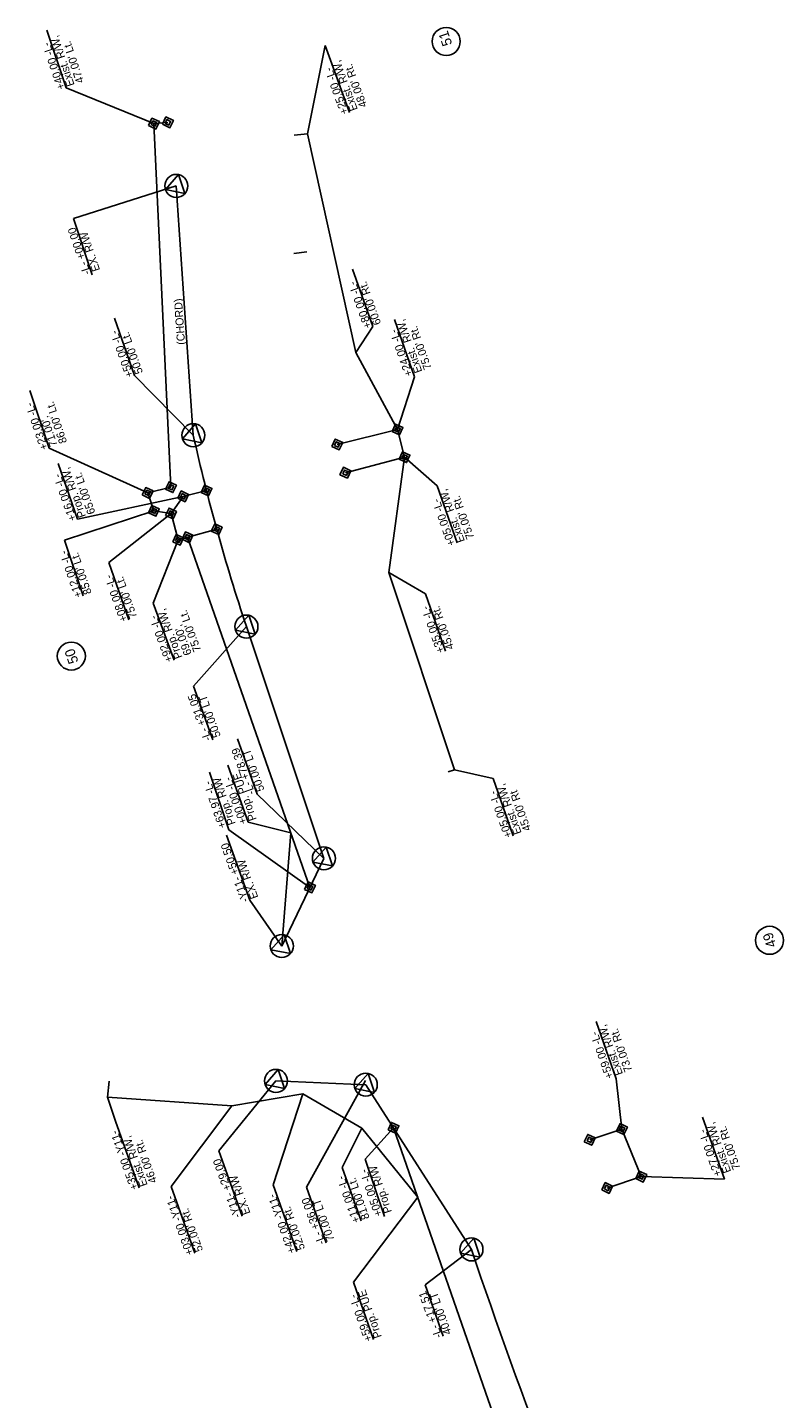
# Model space of a CAD drawing. Extents: x 1610947 to 1617684, y 899814 to 904658.
# Drawn here: x 1615897 to 1616369, y 903801 to 904658 of the extents above; entities that cross this region are included whole.
import ezdxf

# ---------------------------------------------------------------- set-up
doc = ezdxf.new("R2010")
doc.units = 0
for name, color, linetype in [('Prop Conc 1ft 6in Curb and Gutter', 7, 'Continuous'), ('Prop EOT Dash', 7, 'Continuous'), ('Prop Hatching', 7, 'Continuous'), ('Prop Horizontal Alignment Curve and Spiral Data', 7, 'Continuous'), ('Prop Horizontal Alignment Direction Label', 7, 'Continuous'), ('Prop Horizontal Alignment Tick Label', 7, 'Continuous'), ('Prop Horizontal Alignment Tick Large', 7, 'Continuous'), ('Prop Horizontal Alignment Tick Small', 7, 'Continuous'), ('Prop ROW Marker CELL', 7, 'Continuous'), ('Prop ROW RW Lines', 7, 'Continuous'), ('Prop ROW Station Offsets', 7, 'Continuous'), ('Scratch_Level_3', 7, 'Continuous'), ('Scratch_Level_8', 7, 'Continuous'), ('Typical Terminator CELL', 7, 'Continuous')]:
    doc.layers.add(name, color=color, linetype=linetype)

msp = doc.modelspace()

# ---------------------------------------------------------------- linework, layer by layer
at = {"layer": 'Prop Conc 1ft 6in Curb and Gutter'}
for p, q in [((1616082.67, 904646.44), (1616071.76, 904591.28)), ((1616082.67, 904646.44), (1616097.89, 904604.73)), ((1616099.82, 904506.76), (1616112.47, 904471.01)), ((1616145.36, 904303.99), (1616158, 904268.24)), ((1616022.04, 904197.04), (1616034.69, 904161.29)), ((1616187.59, 904188.55), (1616200.24, 904152.81)), ((1615951.85, 903974.58), (1615966.6, 903932.87)), ((1616093.4, 903945.73), (1616105.25, 903912.24)), ((1616050.2, 903934.9), (1616064.95, 903893.2)), ((1615986.48, 903933.79), (1616001.22, 903892.08)), ((1616100.35, 903873.94), (1616140.55, 903927.03)), ((1616100.35, 903873.94), (1616112.89, 903838.16))]:
    msp.add_line(p, q, dxfattribs=at)
for points in [[(1616112.47, 904471.01), (1616101.91, 904454.84)], [(1616145.36, 904303.99), (1616122.46, 904317.27)], [(1616187.59, 904188.55), (1616163.62, 904194.12)], [(1616034.69, 904161.29), (1616061.34, 904154.66)], [(1615951.85, 903974.58), (1615946.8, 903989.62)], [(1616050.2, 903934.9), (1616068.76, 903991.57)], [(1615986.48, 903933.79), (1616024.45, 903984.24)], [(1616093.4, 903945.73), (1616105.62, 903970.18)]]:
    msp.add_lwpolyline(points, dxfattribs=at)
at = {"layer": 'Prop EOT Dash'}
for points in [[(1615972.41, 904596.48), (1615974.56, 904601.1), (1615979.18, 904598.95), (1615977.03, 904594.34)], [(1615974.11, 904597.1), (1615975.18, 904599.41), (1615977.49, 904598.33), (1615976.41, 904596.03)], [(1615981.14, 904597.27), (1615983.29, 904601.88), (1615987.9, 904599.74), (1615985.76, 904595.12)], [(1615982.83, 904597.88), (1615983.9, 904600.19), (1615986.21, 904599.12), (1615985.14, 904596.81)], [(1616124.55, 904405.37), (1616126.69, 904409.99), (1616131.31, 904407.84), (1616129.16, 904403.22)], [(1616126.24, 904405.99), (1616127.31, 904408.3), (1616129.62, 904407.22), (1616128.54, 904404.91)], [(1616086.93, 904396.1), (1616089.08, 904400.71), (1616093.69, 904398.56), (1616091.54, 904393.95)], [(1616088.62, 904396.71), (1616089.69, 904399.02), (1616092, 904397.95), (1616090.93, 904395.64)], [(1616128.94, 904388.16), (1616131.09, 904392.78), (1616135.7, 904390.63), (1616133.56, 904386.02)], [(1616130.63, 904388.78), (1616131.7, 904391.09), (1616134.01, 904390.01), (1616132.94, 904387.71)], [(1616091.98, 904378.4), (1616094.13, 904383.02), (1616098.75, 904380.87), (1616096.6, 904376.25)], [(1616093.68, 904379.02), (1616094.75, 904381.33), (1616097.06, 904380.25), (1616095.98, 904377.94)], [(1615983.05, 904369.39), (1615985.19, 904374), (1615989.81, 904371.86), (1615987.66, 904367.24)], [(1615984.74, 904370), (1615985.81, 904372.31), (1615988.12, 904371.24), (1615987.04, 904368.93)], [(1616005.21, 904367.35), (1616007.35, 904371.96), (1616011.97, 904369.82), (1616009.82, 904365.2)], [(1615968.48, 904365.78), (1615970.63, 904370.4), (1615975.25, 904368.25), (1615973.1, 904363.64)], [(1615970.18, 904366.4), (1615971.25, 904368.71), (1615973.56, 904367.63), (1615972.48, 904365.33)], [(1615990.67, 904363.66), (1615992.82, 904368.27), (1615997.43, 904366.12), (1615995.28, 904361.51)], [(1615992.36, 904364.27), (1615993.43, 904366.58), (1615995.74, 904365.51), (1615994.67, 904363.2)], [(1616006.9, 904367.96), (1616007.97, 904370.27), (1616010.28, 904369.2), (1616009.21, 904366.89)], [(1615972.35, 904354.57), (1615974.5, 904359.19), (1615979.11, 904357.04), (1615976.96, 904352.42)], [(1615974.04, 904355.19), (1615975.11, 904357.5), (1615977.42, 904356.42), (1615976.35, 904354.11)], [(1615983.1, 904352.94), (1615985.25, 904357.56), (1615989.87, 904355.41), (1615987.72, 904350.79)], [(1615984.79, 904353.56), (1615985.87, 904355.87), (1615988.17, 904354.79), (1615987.1, 904352.48)], [(1616011.62, 904343.14), (1616013.77, 904347.76), (1616018.39, 904345.61), (1616016.24, 904340.99)], [(1616013.31, 904343.76), (1616014.39, 904346.07), (1616016.7, 904344.99), (1616015.62, 904342.68)], [(1615987.53, 904336.48), (1615989.67, 904341.1), (1615994.29, 904338.95), (1615992.14, 904334.34)], [(1615989.22, 904337.1), (1615990.29, 904339.41), (1615992.6, 904338.33), (1615991.53, 904336.03)], [(1615993.31, 904338.08), (1615995.46, 904342.7), (1616000.07, 904340.55), (1615997.93, 904335.93)], [(1615995, 904338.7), (1615996.07, 904341.01), (1615998.38, 904339.93), (1615997.31, 904337.62)], [(1616069.87, 904119.41), (1616072.02, 904124.03), (1616076.63, 904121.88), (1616074.49, 904117.26)], [(1616071.56, 904120.03), (1616072.63, 904122.34), (1616074.94, 904121.26), (1616073.87, 904118.95)], [(1616122.02, 903969.23), (1616124.17, 903973.85), (1616128.78, 903971.7), (1616126.63, 903967.08)], [(1616123.71, 903969.85), (1616124.78, 903972.16), (1616127.09, 903971.08), (1616126.02, 903968.77)], [(1616264.78, 903968.45), (1616266.93, 903973.07), (1616271.54, 903970.92), (1616269.4, 903966.3)], [(1616266.47, 903969.07), (1616267.55, 903971.37), (1616269.85, 903970.3), (1616268.78, 903967.99)], [(1616244.63, 903961.71), (1616246.77, 903966.33), (1616251.39, 903964.18), (1616249.24, 903959.56)], [(1616246.32, 903962.33), (1616247.39, 903964.64), (1616249.7, 903963.56), (1616248.63, 903961.26)], [(1616276.83, 903938.74), (1616278.98, 903943.35), (1616283.59, 903941.2), (1616281.44, 903936.59)], [(1616255.51, 903931.61), (1616257.66, 903936.23), (1616262.27, 903934.08), (1616260.13, 903929.46)], [(1616257.2, 903932.23), (1616258.28, 903934.54), (1616260.58, 903933.46), (1616259.51, 903931.15)], [(1616278.52, 903939.35), (1616279.59, 903941.66), (1616281.9, 903940.59), (1616280.83, 903938.28)]]:
    msp.add_lwpolyline(points, close=True, dxfattribs=at)
at = {"layer": 'Prop Hatching'}
for centre in [(1616158.36, 904649.05), (1615924.17, 904265.11), (1616360.36, 904087.56)]:
    msp.add_circle(centre, 8.75, dxfattribs=at)
at = {"layer": 'Prop Horizontal Alignment Curve and Spiral Data'}
for p, q in [((1615915.92, 904385.35), (1615928.06, 904350.69)), ((1615947.52, 904323.53), (1615960.05, 904287.75)), ((1615975.37, 904298.15), (1615988.37, 904262.52))]:
    msp.add_line(p, q, dxfattribs=at)
for points in [[(1615928.06, 904350.69), (1615994.05, 904364.89)], [(1615947.52, 904323.53), (1615986.48, 904354.18)], [(1615975.37, 904298.15), (1615990.91, 904337.72)]]:
    msp.add_lwpolyline(points, dxfattribs=at)
at = {"layer": 'Prop Horizontal Alignment Direction Label'}
for p, q in [((1615975.8, 904597.72), (1615984.52, 904598.5)), ((1615986.43, 904370.62), (1615975.8, 904597.72)), ((1615986.43, 904370.62), (1615971.87, 904367.02)), ((1615975.73, 904355.8), (1615971.87, 904367.02)), ((1615986.48, 904354.18), (1615975.73, 904355.8)), ((1616073.25, 904120.64), (1615996.69, 904339.31)), ((1616257.65, 903591.25), (1616125.4, 903970.47))]:
    msp.add_line(p, q, dxfattribs=at)
at = {"layer": 'Prop Horizontal Alignment Tick Label'}
for p, q in [((1615908.85, 904656.06), (1615920.91, 904620.11)), ((1615920.91, 904620.11), (1615975.8, 904597.72)), ((1615898.25, 904430.99), (1615910.31, 904395.04)), ((1615919.95, 904337.52), (1615931.62, 904302.71)), ((1616010.55, 904192.58), (1616022.61, 904156.63)), ((1616022.61, 904156.63), (1616073.25, 904120.64)), ((1616107.71, 903950.91), (1616125.4, 903970.47)), ((1616107.71, 903950.91), (1616119.77, 903914.96))]:
    msp.add_line(p, q, dxfattribs=at)
for points in [[(1615910.31, 904395.04), (1615971.87, 904367.02)], [(1615919.95, 904337.52), (1615975.73, 904355.8)]]:
    msp.add_lwpolyline(points, dxfattribs=at)
at = {"layer": 'Prop Horizontal Alignment Tick Large'}
for p, q in [((1615994.05, 904364.89), (1615986.48, 904354.18)), ((1616008.59, 904368.58), (1615994.05, 904364.89)), ((1615990.91, 904337.72), (1615986.48, 904354.18)), ((1616015.01, 904344.37), (1615990.91, 904337.72))]:
    msp.add_line(p, q, dxfattribs=at)
at = {"layer": 'Prop ROW Marker CELL'}
for p, q in [((1615975.8, 904597.72), (1615975.8, 904597.72)), ((1615984.52, 904598.5), (1615984.52, 904598.5)), ((1615989.74, 904558.81), (1615989.74, 904558.81)), ((1616127.93, 904406.61), (1616127.93, 904406.61)), ((1616000.36, 904403.09), (1616000.36, 904403.09)), ((1616090.31, 904397.33), (1616090.31, 904397.33)), ((1616132.32, 904389.4), (1616132.32, 904389.4)), ((1616095.37, 904379.63), (1616095.37, 904379.63)), ((1615971.87, 904367.02), (1615971.87, 904367.02)), ((1615986.43, 904370.62), (1615986.43, 904370.62)), ((1615994.05, 904364.89), (1615994.05, 904364.89)), ((1616008.59, 904368.58), (1616008.59, 904368.58)), ((1615975.73, 904355.8), (1615975.73, 904355.8)), ((1615986.48, 904354.18), (1615986.48, 904354.18)), ((1615990.91, 904337.72), (1615990.91, 904337.72)), ((1615996.69, 904339.31), (1615996.69, 904339.31)), ((1616015.01, 904344.37), (1616015.01, 904344.37)), ((1616033.56, 904283.55), (1616033.56, 904283.55)), ((1616081.96, 904138.77), (1616081.96, 904138.77)), ((1616073.25, 904120.64), (1616073.25, 904120.64)), ((1616055.66, 904084.01), (1616055.66, 904084.01)), ((1616052.01, 903999.76), (1616052.01, 903999.76)), ((1616108.13, 903997.38), (1616108.13, 903997.38)), ((1616125.4, 903970.47), (1616125.4, 903970.47)), ((1616268.16, 903969.68), (1616268.16, 903969.68)), ((1616248.01, 903962.95), (1616248.01, 903962.95)), ((1616280.21, 903939.97), (1616280.21, 903939.97)), ((1616258.89, 903932.84), (1616258.89, 903932.84)), ((1616174.14, 903894.51), (1616174.14, 903894.51))]:
    msp.add_line(p, q, dxfattribs=at)
for points in [[(1615995.14, 904554.03), (1615982.91, 904556.52), (1615991.16, 904565.88)], [(1616005.77, 904398.31), (1615993.54, 904400.8), (1616001.79, 904410.16)], [(1616038.96, 904278.77), (1616026.74, 904281.26), (1616034.99, 904290.62)], [(1616087.36, 904133.99), (1616075.13, 904136.48), (1616083.38, 904145.84)], [(1616061.06, 904079.23), (1616048.83, 904081.72), (1616057.08, 904091.08)], [(1616057.41, 903994.98), (1616045.19, 903997.47), (1616053.44, 904006.83)], [(1616113.53, 903992.6), (1616101.3, 903995.09), (1616109.55, 904004.45)], [(1616179.55, 903889.73), (1616167.32, 903892.22), (1616175.57, 903901.58)]]:
    msp.add_lwpolyline(points, close=True, dxfattribs=at)
for centre in [(1615989.74, 904558.81), (1616000.36, 904403.09), (1616033.56, 904283.55), (1616081.96, 904138.77), (1616055.66, 904084.01), (1616052.01, 903999.76), (1616108.13, 903997.38), (1616174.14, 903894.51)]:
    msp.add_circle(centre, 7.2, dxfattribs=at)
at = {"layer": 'Prop ROW RW Lines'}
for p, q in [((1616000.36, 904403.09), (1615989.74, 904558.81)), ((1616071.35, 904517.66), (1616063.19, 904516.58)), ((1616081.96, 904138.77), (1616033.56, 904283.55)), ((1616055.66, 904084.01), (1616081.96, 904138.77)), ((1616052.01, 903999.76), (1616108.13, 903997.38)), ((1616174.14, 903894.51), (1616108.13, 903997.38))]:
    msp.add_line(p, q, dxfattribs=at)
for centre, radius, start, end in [((1617171.66, 904663.97), 1200, 192.55619, 198.48273), ((1619057.34, 904858.25), 3040, 198.48273, 204.08027)]:
    msp.add_arc(centre, radius, start, end, dxfattribs=at)
at = {"layer": 'Prop ROW Station Offsets'}
for p, q in [((1615925.47, 904538.37), (1615989.74, 904558.81)), ((1615925.47, 904538.37), (1615937.22, 904503.34)), ((1615951.04, 904476.14), (1615963.72, 904440.41)), ((1616000.58, 904246.22), (1616033.56, 904283.55)), ((1616000.58, 904246.22), (1616012.56, 904212.71)), ((1616027.91, 904213.45), (1616040.31, 904178.78)), ((1616040.31, 904178.78), (1616081.96, 904138.77)), ((1616021.14, 904153.27), (1616035.71, 904112.54)), ((1616035.71, 904112.54), (1616055.66, 904084.01)), ((1616016.27, 903956.02), (1616052.01, 903999.76)), ((1616071, 903933.38), (1616107.84, 903999.98)), ((1616016.27, 903956.02), (1616030.84, 903915.29)), ((1616071, 903933.38), (1616083.34, 903898.64)), ((1616145.13, 903872.27), (1616156.47, 903840.32))]:
    msp.add_line(p, q, dxfattribs=at)
for points in [[(1615963.72, 904440.41), (1616000.36, 904403.09)], [(1616145.13, 903872.27), (1616174.14, 903894.51), (1616174.14, 903894.51)]]:
    msp.add_lwpolyline(points, dxfattribs=at)
at = {"layer": 'Scratch_Level_3'}
for p, q in [((1616071.76, 904591.28), (1616063.48, 904590.53)), ((1616101.91, 904454.84), (1616071.76, 904591.28)), ((1616127.93, 904406.61), (1616101.91, 904454.84)), ((1616122.46, 904317.27), (1616132.32, 904389.4)), ((1616163.62, 904194.12), (1616122.46, 904317.27)), ((1616159.52, 904192.75), (1616163.62, 904194.12)), ((1616055.66, 904084.01), (1616061.34, 904154.66)), ((1615946.8, 903989.62), (1615947.72, 903999.64)), ((1616024.45, 903984.24), (1615946.8, 903989.62)), ((1616068.76, 903991.57), (1616024.45, 903984.24)), ((1616105.62, 903970.18), (1616068.76, 903991.57)), ((1616140.55, 903927.03), (1616105.62, 903970.18))]:
    msp.add_line(p, q, dxfattribs=at)
at = {"layer": 'Scratch_Level_8'}
for p, q in [((1616126.09, 904475.33), (1616138.62, 904439.54)), ((1616138.62, 904439.54), (1616127.93, 904406.61)), ((1616152.72, 904371.53), (1616132.32, 904389.4)), ((1616152.72, 904371.53), (1616165.26, 904335.75)), ((1616252.06, 904036.87), (1616264.6, 904001.08)), ((1616264.6, 904001.08), (1616268.16, 903969.68)), ((1616318.55, 903977.09), (1616332.13, 903938.33)), ((1616332.13, 903938.33), (1616280.21, 903939.97))]:
    msp.add_line(p, q, dxfattribs=at)
at = {"layer": 'Typical Terminator CELL'}
for p, q in [((1616127.93, 904406.61), (1616090.31, 904397.33)), ((1616132.32, 904389.4), (1616127.93, 904406.61)), ((1616095.37, 904379.63), (1616132.32, 904389.4)), ((1616268.16, 903969.68), (1616248.01, 903962.95)), ((1616280.21, 903939.97), (1616268.16, 903969.68)), ((1616258.89, 903932.84), (1616280.21, 903939.97))]:
    msp.add_line(p, q, dxfattribs=at)

# ---------------------------------------------------------------- texts
at = {"layer": 'Prop Conc 1ft 6in Curb and Gutter'}
for s, rotation, p in [('Exist. R/W,', 110.05109, (1616103.17, 904606.65)), ('+25.00 -L-', 110.05109, (1616097.3, 904604.51)), ("48.00' Rt.", 110.05109, (1616109.05, 904608.8)), ('+80.00 -L-', 109.47574, (1616111.88, 904470.8)), ("60.00' Rt.", 109.47574, (1616117.77, 904472.88)), ('+35.00 -L-', 109.47574, (1616157.41, 904268.03)), ("45.00' Rt.", 109.47574, (1616163.3, 904270.11)), ('Prop. PUE', 109.47574, (1616039.99, 904163.17)), ('+00.00 -L-', 109.47574, (1616034.1, 904161.09)), ('Exist. R/W,', 109.47574, (1616205.54, 904154.68)), ('+05.00 -L-', 109.47574, (1616199.65, 904152.6)), ("45.00' Rt", 109.47574, (1616211.43, 904156.77)), ('+35.00 -Y11-', 109.47574, (1615966.01, 903932.66)), ('Exist. R/W,', 109.47574, (1615971.9, 903934.75)), ("46.00' Rt.", 109.47574, (1615977.79, 903936.83)), ('+11.00 -L-', 109.47574, (1616104.66, 903912.03)), ("81.00' Lt.", 109.47574, (1616110.55, 903914.12)), ('+03.00 -Y11-', 109.47574, (1616000.63, 903891.88)), ('+42.00 -Y11-', 109.47574, (1616064.36, 903892.99)), ("52.00' Rt.", 109.47574, (1616006.53, 903893.96)), ("52.00' Rt.", 109.47574, (1616070.25, 903895.08)), ('+59.00 -L-', 109.30477, (1616112.3, 903837.95)), ('Prop. PUE', 109.30477, (1616118.2, 903840.02))]:
    msp.add_text(s, height=5, rotation=rotation, dxfattribs=at).set_placement(p)
at = {"layer": 'Prop Hatching'}
for s, p in [('51', (1616162.23, 904647.42)), ('50', (1615928.69, 904261.56)), ('49', (1616364.81, 904084.25))]:
    msp.add_text(s, height=6.25, rotation=109.01556, dxfattribs=at).set_placement(p)
at = {"layer": 'Prop Horizontal Alignment Curve and Spiral Data'}
for s, rotation, p in [('Prop. R/W,', 109.30477, (1615933.37, 904352.55)), ("65.00' Lt.", 109.30477, (1615939.27, 904354.62)), ('+16.00 -L-', 109.30477, (1615927.47, 904350.49)), ('+08.00 -L-', 109.30477, (1615959.46, 904287.54)), ("75.00' Lt.", 109.30477, (1615965.36, 904289.61)), ('Prop. R/W,', 110.05109, (1615993.65, 904264.45)), ("75.00' Lt.", 110.05109, (1616005.4, 904268.74)), ('+92.00 -L-', 110.05109, (1615987.78, 904262.31)), ("69.00',", 110.05109, (1615999.53, 904266.6))]:
    msp.add_text(s, height=5, rotation=rotation, dxfattribs=at).set_placement(p)
at = {"layer": 'Prop Horizontal Alignment Tick Label'}
for s, p in [('+40.00 -L-', (1615920.31, 904619.91)), ('Exist. R/W,', (1615926.24, 904621.9)), ("47.00' Lt.", (1615932.17, 904623.88)), ('+23.00 -L-', (1615909.71, 904394.84)), ("86.00' Lt.", (1615921.57, 904398.81)), ("71.00',", (1615915.64, 904396.83)), ('+12.00 -L-', (1615931.03, 904302.51)), ("85.00' Lt.", (1615936.96, 904304.5)), ('+63.97 -L-', (1616021.01, 904158.53)), ('Prop. R/W', (1616026.94, 904160.52)), ('+05.00 -L-', (1616118.56, 903916.06)), ('Prop. R/W', (1616124.49, 903918.04))]:
    msp.add_text(s, height=5, rotation=108.54317, dxfattribs=at).set_placement(p)
at = {"layer": 'Prop Horizontal Alignment Tick Small'}
msp.add_text('(CHORD)', height=5, rotation=93.90477, dxfattribs=at).set_placement((1615995.25, 904459.71))
at = {"layer": 'Prop ROW Station Offsets'}
for s, rotation, p in [('-L- +00.00', 108.54317, (1615936.25, 904504.31)), ('EX. R/W', 108.54317, (1615942.17, 904506.3)), ('+50.00 -L-', 109.54863, (1615963.13, 904440.2)), ("50.00' Lt.", 109.54863, (1615969.02, 904442.29)), ('-L- +31.05', 109.68596, (1616011.73, 904213.1)), ("50.00' LT", 109.68596, (1616017.61, 904215.21)), ('-L- +78.39', 109.68596, (1616039, 904179.42)), ("50.00' LT", 109.68596, (1616044.89, 904181.52)), ('-Y11- +50.50', 109.68596, (1616035.12, 904112.33)), ('EX. R/W', 109.68596, (1616041.01, 904114.44)), ('-Y11- +29.00', 109.68596, (1616030.25, 903915.08)), ('EX. R/W', 109.68596, (1616036.14, 903917.18)), ('-L- +36.00', 109.54863, (1616082.75, 903898.44)), ("70.00' LT", 109.54863, (1616088.64, 903900.53)), ('-L- +17.51', 109.54863, (1616155.88, 903840.11)), ("40.00' LT", 109.54863, (1616161.77, 903842.2))]:
    msp.add_text(s, height=5, rotation=rotation, dxfattribs=at).set_placement(p)
at = {"layer": 'Scratch_Level_8'}
for s, p in [('Exist.  R/W,', (1616143.44, 904442.92)), ('+24.00 -L-', (1616137.54, 904440.86)), ("75.00' Rt.", (1616149.33, 904444.99)), ('+05.00 -L-', (1616164.16, 904334.93)), ('Exist.  R/W,', (1616170.06, 904337)), ("75.00' Rt.", (1616175.96, 904339.07)), ('+59.00 -L-', (1616262.9, 904002.1)), ('Exist. R/W,', (1616268.8, 904004.16)), ("73.00' Rt.", (1616274.7, 904006.23)), ('+27.00 -L-', (1616330.5, 903941.1)), ('Exist. R/W,', (1616336.4, 903943.16)), ("75.00' Rt.", (1616342.29, 903945.23))]:
    msp.add_text(s, height=5, rotation=109.30477, dxfattribs=at).set_placement(p)

doc.saveas('drawing.dxf')
